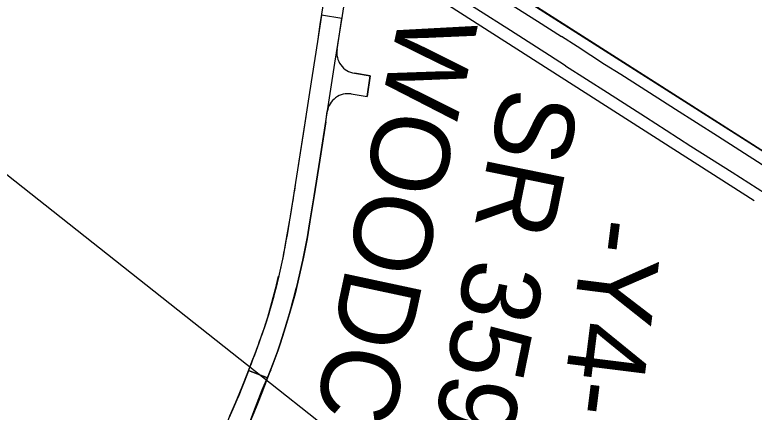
# Model space of a CAD drawing. Extents: x 1750583 to 1791140, y 783580 to 827376.
# Drawn here: x 1782431 to 1783138, y 813741 to 814121 of the extents above; entities that cross this region are included whole.
import ezdxf

# ---------------------------------------------------------------- set-up
doc = ezdxf.new("R2010")
doc.units = 0
for name, color, linetype in [('Exist CMT EOP', 7, 'Continuous'), ('Prop Dimension Text', 7, 'Continuous'), ('Prop EOT', 7, 'Continuous'), ('Prop Shade Heavy', 7, 'Continuous'), ('Sheet Plan Layout CELL', 7, 'Continuous')]:
    doc.layers.add(name, color=color, linetype=linetype)

msp = doc.modelspace()

# ---------------------------------------------------------------- linework, layer by layer
at = {"layer": 'Exist CMT EOP'}
for p, q in [((1782675.37, 813782.04), (1782682.09, 813799.73)), ((1782652.92, 813778.24), (1782644.03, 813755.44))]:
    msp.add_line(p, q, dxfattribs=at)
for points in [[(1782734.23, 814187.61), (1782728.02, 814148.04), (1782722.36, 814112.03), (1782719.85, 814095.74), (1782712.33, 814047.16), (1782706.26, 814007.67), (1782699.07, 813961.06)], [(1782957.05, 814072.69), (1782941.75, 814082.49), (1782904.59, 814106.27), (1782872.37, 814126.89), (1782853.79, 814138.65), (1782835.42, 814150.23), (1782806.48, 814168.98), (1782784.48, 814182.91)], [(1782832.73, 814177.58), (1782865.06, 814156.93), (1782903.76, 814132.24), (1782930.45, 814115.26), (1782953.36, 814100.59)], [(1782716.95, 813948.36), (1782722.21, 813982.3), (1782730.09, 814033.69), (1782736.6, 814075.08), (1782743.83, 814120.73), (1782749.51, 814158.26)], [(1783312.22, 813870.98), (1783270.66, 813897.48), (1783229.11, 813924.07), (1783187.82, 813950.57), (1783145.4, 813977.8), (1783102.46, 814005.18), (1783062.43, 814030.76), (1783037.57, 814046.7), (1783010.11, 814064.34), (1782994.61, 814073.9), (1782968.36, 814091.08), (1782953.36, 814100.59)], [(1782957.05, 814072.69), (1782997.32, 814047.07), (1783033.64, 814023.73), (1783053.56, 814011.03), (1783077.16, 813995.81), (1783116.5, 813970.95), (1783156.27, 813945.27), (1783197.33, 813919.23), (1783238.94, 813892.35), (1783280.65, 813865.79), (1783320.67, 813840.18), (1783362.13, 813813.73), (1783381.93, 813800.87)], [(1782682.52, 813871.32), (1782679.39, 813859), (1782675.06, 813842.21), (1782672.19, 813831.96), (1782668.92, 813822.02), (1782663.28, 813805.79), (1782658.53, 813792.76)], [(1782623.35, 813704.26), (1782623.39, 813704.36), (1782626.9, 813713.77), (1782632.27, 813727.44), (1782636.31, 813737.6), (1782641.85, 813750.8), (1782647.94, 813765.44), (1782653.31, 813779.27), (1782658.53, 813792.76)], [(1782594.39, 813580.74), (1782599.7, 813593.6), (1782605.42, 813607.2), (1782611.38, 813620.83), (1782615.3, 813631.65), (1782618.86, 813639.68), (1782626.38, 813658.87), (1782630.77, 813669.73), (1782635.61, 813681.75), (1782640.93, 813695.18), (1782645.99, 813707.93), (1782651.1, 813721.07), (1782656.25, 813734.24), (1782660.61, 813746.04), (1782667.1, 813762.5), (1782673.14, 813776.71), (1782675.73, 813781.86)]]:
    msp.add_lwpolyline(points, dxfattribs=at)
for points in [[(1781123.7, 814794.56), (1781151.95, 814749.7), (1781175.35, 814711.94), (1781204.02, 814667.22), (1781230.05, 814626.42), (1781255.51, 814585.11), (1781282.93, 814541.39), (1781309.04, 814500.81), (1781338.07, 814453.82), (1781362.44, 814415.66), (1781389.1, 814373.22), (1781417.2, 814328.4), (1781443.82, 814286), (1781469.22, 814245.27), (1781496.33, 814201.88), (1781523.28, 814159.28), (1781551.49, 814114.9), (1781575, 814076.8), (1781602.27, 814034.47), (1781628.68, 813992.42), (1781657.71, 813946.44), (1781682.97, 813906.24), (1781710.54, 813862.11), (1781734.73, 813823.58), (1781763.09, 813779.24), (1781788.41, 813738.38), (1781814.81, 813696.35), (1781842.37, 813653.36), (1781868.91, 813610.68), (1781895.83, 813568.71), (1781924.39, 813523.58), (1781950.61, 813481.8), (1781976.68, 813442.67), (1782004.37, 813401.37), (1782031.99, 813360.12), (1782060.77, 813317.53), (1782089.19, 813276.64), (1782119.2, 813233.31), (1782146.2, 813195.67), (1782175.13, 813155.14), (1782204.07, 813115.4), (1782233.24, 813075.72), (1782263.79, 813034.43), (1782294.03, 812994.29), (1782325.04, 812953.86), (1782354.41, 812916.21), (1782385, 812877.38), (1782417.21, 812837.26), (1782449.43, 812797.65), (1782479.54, 812761.76), (1782513.17, 812720.66), (1782543.05, 812684.98), (1782576.35, 812645.89), (1782608.48, 812608.74), (1782640.69, 812571.37), (1782677.39, 812530.96), (1782710.34, 812494.65), (1782741.2, 812460.83), (1782775.54, 812424.09), (1782810.15, 812387.02), (1782844.36, 812350.73), (1782880.69, 812313.19), (1782914.85, 812277.64), (1782949.87, 812242.16), (1782985.13, 812206.92), (1783022.44, 812170.42), (1783054.86, 812138.57), (1783094.75, 812100.54), (1783130.02, 812066.91), (1783162.74, 812036.24), (1783200.85, 812001.49), (1783239.6, 811965.96), (1783275.52, 811933.35), (1783312.46, 811900.79)], [(1782699.07, 813961.06), (1782695.87, 813940.8), (1782687.6, 813893.23), (1782679.87, 813859.05), (1782675.04, 813841.16), (1782666.84, 813815.75), (1782652.92, 813778.24)], [(1782682.09, 813799.73), (1782691.65, 813830.13), (1782703.07, 813873.65), (1782710.99, 813912.33), (1782716.95, 813948.36)]]:
    msp.add_spline(points, degree=3, dxfattribs=at)
at = {"layer": 'Prop EOT'}
for p, q in [((1782664.72, 814298.51), (1783161.32, 813980.96)), ((1782641.02, 814261.44), (1783137.62, 813943.89)), ((1782723.75, 814121.03), (1782719.85, 814095.74)), ((1782743.39, 814117.93), (1782723.75, 814121.03)), ((1782738.7, 814088.31), (1782743.39, 814117.93)), ((1782719.85, 814095.74), (1782712.33, 814047.16)), ((1782755.33, 814065.43), (1782770.52, 814063.03)), ((1782770.52, 814063.03), (1782767.41, 814043.28)), ((1782712.33, 814047.16), (1782708.5, 814022.2)), ((1782752.25, 814045.67), (1782767.41, 814043.28)), ((1782727.86, 814019.14), (1782729.36, 814028.94))]:
    msp.add_line(p, q, dxfattribs=at)
for points in [[(1782708.5, 814022.2), (1782701.56, 813977.16), (1782698.42, 813956.92), (1782694.18, 813930.37), (1782692.38, 813919.73), (1782689.87, 813905.54), (1782687.1, 813890.63), (1782683.3, 813873.14), (1782680.34, 813860.95), (1782676.08, 813844.76), (1782672.99, 813834.31), (1782669.89, 813824.5), (1782667.01, 813816.21), (1782664.33, 813808.79), (1782662.52, 813803.68), (1782659.32, 813794.9), (1782658.53, 813792.74), (1782655.75, 813785.57), (1782653.99, 813781.01)], [(1782727.86, 814019.14), (1782722.21, 813982.3), (1782716.95, 813948.36), (1782712.79, 813923.21), (1782710.11, 813907.18), (1782706.61, 813889.5), (1782702.8, 813872.5), (1782698.51, 813854.49), (1782696.15, 813845.58), (1782693.32, 813835.57), (1782691.33, 813829.11), (1782689.07, 813821.9), (1782686.5, 813813.75), (1782683.94, 813805.6), (1782682.16, 813799.93), (1782677.29, 813787.09), (1782675.13, 813781.44), (1782672.16, 813774.06)]]:
    msp.add_lwpolyline(points, dxfattribs=at)
for centre, start, end in [((1782758.45, 814085.18), 171.00203, 261.03336), ((1782749.13, 814025.91), 81.03336, 171.28117)]:
    msp.add_arc(centre, 20, start, end, dxfattribs=at)
for points in [[(1782653.99, 813781.01), (1782653.75, 813780.38), (1782653.52, 813779.76), (1782653.28, 813779.14), (1782653.05, 813778.51), (1782652.81, 813777.89), (1782652.57, 813777.27), (1782652.34, 813776.65), (1782652.1, 813776.02), (1782651.86, 813775.4), (1782651.62, 813774.78), (1782651.38, 813774.16), (1782651.14, 813773.54), (1782650.9, 813772.92), (1782650.66, 813772.29), (1782650.41, 813771.67), (1782650.17, 813771.05), (1782649.93, 813770.43), (1782649.68, 813769.81), (1782649.44, 813769.19), (1782649.19, 813768.57), (1782648.95, 813767.95), (1782648.7, 813767.34), (1782648.45, 813766.72), (1782648.21, 813766.1), (1782647.96, 813765.48), (1782647.71, 813764.86), (1782647.46, 813764.24), (1782647.21, 813763.62), (1782646.96, 813763.01), (1782646.71, 813762.39), (1782646.46, 813761.77), (1782646.21, 813761.16), (1782645.96, 813760.54), (1782645.7, 813759.92), (1782645.45, 813759.31), (1782645.19, 813758.69), (1782644.94, 813758.07), (1782644.68, 813757.46), (1782644.43, 813756.84), (1782644.17, 813756.23), (1782643.92, 813755.61), (1782643.66, 813755), (1782643.4, 813754.38), (1782643.14, 813753.77), (1782642.88, 813753.16), (1782642.62, 813752.54), (1782642.36, 813751.93), (1782642.1, 813751.32), (1782641.84, 813750.7), (1782641.58, 813750.09), (1782641.32, 813749.48), (1782641.05, 813748.87), (1782640.79, 813748.25), (1782640.52, 813747.64), (1782640.26, 813747.03), (1782639.99, 813746.42), (1782639.73, 813745.81), (1782639.46, 813745.2), (1782639.19, 813744.59), (1782638.93, 813743.98), (1782638.66, 813743.37), (1782638.39, 813742.76), (1782638.12, 813742.15), (1782637.85, 813741.54), (1782637.58, 813740.93), (1782637.31, 813740.32), (1782637.04, 813739.71), (1782636.77, 813739.1), (1782636.49, 813738.49), (1782636.21, 813737.86), (1782635.93, 813737.24), (1782635.65, 813736.61), (1782635.1, 813735.37)], [(1782672.16, 813774.06), (1782671.93, 813773.41), (1782671.69, 813772.77), (1782671.46, 813772.13), (1782671.22, 813771.49), (1782670.99, 813770.84), (1782670.75, 813770.2), (1782670.51, 813769.56), (1782670.27, 813768.92), (1782670.04, 813768.28), (1782669.8, 813767.64), (1782669.56, 813767), (1782669.32, 813766.35), (1782669.08, 813765.71), (1782668.83, 813765.07), (1782668.59, 813764.43), (1782668.35, 813763.79), (1782668.11, 813763.15), (1782667.86, 813762.51), (1782667.62, 813761.88), (1782667.37, 813761.24), (1782667.13, 813760.6), (1782666.88, 813759.96), (1782666.63, 813759.32), (1782666.39, 813758.68), (1782666.14, 813758.04), (1782665.89, 813757.41), (1782665.64, 813756.77), (1782665.39, 813756.13), (1782665.14, 813755.5), (1782664.89, 813754.86), (1782664.64, 813754.22), (1782664.39, 813753.59), (1782664.13, 813752.95), (1782663.88, 813752.31), (1782663.63, 813751.68), (1782663.37, 813751.04), (1782663.12, 813750.41), (1782662.86, 813749.77), (1782662.61, 813749.14), (1782662.35, 813748.5), (1782662.09, 813747.87), (1782661.83, 813747.23), (1782661.58, 813746.6), (1782661.32, 813745.97), (1782661.06, 813745.33), (1782660.8, 813744.7), (1782660.54, 813744.07), (1782660.28, 813743.43), (1782660.01, 813742.8), (1782659.75, 813742.17), (1782659.49, 813741.54), (1782659.22, 813740.91), (1782658.96, 813740.27), (1782658.69, 813739.64), (1782658.43, 813739.01), (1782658.16, 813738.38), (1782657.9, 813737.75), (1782657.63, 813737.12), (1782657.36, 813736.49), (1782657.09, 813735.86), (1782656.82, 813735.23), (1782656.55, 813734.6), (1782656.28, 813733.97), (1782656.01, 813733.34), (1782655.74, 813732.71), (1782655.47, 813732.08), (1782655.2, 813731.46), (1782654.93, 813730.83), (1782654.66, 813730.21), (1782654.39, 813729.59), (1782654.12, 813728.98), (1782653.86, 813728.37), (1782653.33, 813727.14)]]:
    msp.add_spline(points, degree=3, dxfattribs=at)
at = {"layer": 'Prop Shade Heavy'}
for p, q in [((1783161.38, 813980.92), (1782664.72, 814298.51)), ((1782641.02, 814261.44), (1783137.68, 813943.86)), ((1782723.75, 814121.03), (1782719.85, 814095.74)), ((1782743.39, 814117.93), (1782723.75, 814121.03)), ((1782738.7, 814088.31), (1782743.39, 814117.93)), ((1782719.85, 814095.74), (1782712.33, 814047.16)), ((1782770.52, 814063.03), (1782755.33, 814065.43)), ((1782767.41, 814043.28), (1782770.52, 814063.03)), ((1782712.33, 814047.16), (1782708.5, 814022.2)), ((1782752.25, 814045.67), (1782767.41, 814043.28)), ((1782727.86, 814019.14), (1782729.36, 814028.94)), ((1782672.16, 813774.06), (1782653.99, 813781.01)), ((1782653.99, 813781.01), (1782672.16, 813774.06))]:
    msp.add_line(p, q, dxfattribs=at)
for points in [[(1782708.5, 814022.2), (1782701.56, 813977.16), (1782698.42, 813956.92), (1782694.18, 813930.37), (1782692.38, 813919.73), (1782689.87, 813905.54), (1782687.1, 813890.63), (1782683.3, 813873.14), (1782680.34, 813860.95), (1782676.08, 813844.76), (1782672.99, 813834.31), (1782669.89, 813824.5), (1782667.01, 813816.21), (1782664.33, 813808.79), (1782662.52, 813803.68), (1782659.32, 813794.9), (1782658.53, 813792.74), (1782655.75, 813785.57), (1782653.99, 813781.01)], [(1782672.16, 813774.06), (1782675.13, 813781.44), (1782677.29, 813787.09), (1782682.16, 813799.93), (1782683.94, 813805.6), (1782686.5, 813813.75), (1782689.07, 813821.9), (1782691.33, 813829.11), (1782693.32, 813835.57), (1782696.15, 813845.58), (1782698.51, 813854.49), (1782702.8, 813872.5), (1782706.61, 813889.5), (1782710.11, 813907.18), (1782712.79, 813923.21), (1782716.95, 813948.36), (1782722.21, 813982.3), (1782727.86, 814019.14)]]:
    msp.add_lwpolyline(points, dxfattribs=at)
for centre, start, end in [((1782758.45, 814085.18), 171.00203, 261.03336), ((1782749.13, 814025.91), 81.03336, 171.28117)]:
    msp.add_arc(centre, 20, start, end, dxfattribs=at)
for points in [[(1782653.99, 813781.01), (1782653.91, 813780.8), (1782653.83, 813780.59), (1782653.75, 813780.38), (1782653.68, 813780.18), (1782653.6, 813779.97), (1782653.52, 813779.76), (1782653.44, 813779.55), (1782653.36, 813779.34), (1782653.28, 813779.14), (1782653.2, 813778.93), (1782653.13, 813778.72), (1782653.05, 813778.51), (1782652.97, 813778.31), (1782652.89, 813778.1), (1782652.81, 813777.89), (1782652.73, 813777.68), (1782652.65, 813777.48), (1782652.57, 813777.27), (1782652.49, 813777.06), (1782652.41, 813776.85), (1782652.34, 813776.65), (1782652.26, 813776.44), (1782652.18, 813776.23), (1782652.1, 813776.02), (1782652.02, 813775.82), (1782651.94, 813775.61), (1782651.86, 813775.4), (1782651.78, 813775.19), (1782651.7, 813774.99), (1782651.62, 813774.78), (1782651.54, 813774.57), (1782651.46, 813774.37), (1782651.38, 813774.16), (1782651.3, 813773.95), (1782651.22, 813773.74), (1782651.14, 813773.54), (1782651.06, 813773.33), (1782650.98, 813773.12), (1782650.9, 813772.92), (1782650.82, 813772.71), (1782650.74, 813772.5), (1782650.66, 813772.29), (1782650.57, 813772.09), (1782650.49, 813771.88), (1782650.41, 813771.67), (1782650.33, 813771.47), (1782650.25, 813771.26), (1782650.17, 813771.05), (1782650.09, 813770.85), (1782650.01, 813770.64), (1782649.93, 813770.43), (1782649.85, 813770.23), (1782649.76, 813770.02), (1782649.68, 813769.81), (1782649.6, 813769.61), (1782649.52, 813769.4), (1782649.44, 813769.19), (1782649.36, 813768.99), (1782649.28, 813768.78), (1782649.19, 813768.57), (1782649.11, 813768.37), (1782649.03, 813768.16), (1782648.95, 813767.95), (1782648.87, 813767.75), (1782648.78, 813767.54), (1782648.7, 813767.34), (1782648.62, 813767.13), (1782648.54, 813766.92), (1782648.45, 813766.72), (1782648.37, 813766.51), (1782648.29, 813766.3), (1782648.21, 813766.1), (1782648.15, 813765.95), (1782648.09, 813765.8), (1782648.03, 813765.65)], [(1782666.23, 813758.28), (1782666.28, 813758.41), (1782666.34, 813758.55), (1782666.39, 813758.68), (1782666.47, 813758.9), (1782666.55, 813759.11), (1782666.63, 813759.32), (1782666.72, 813759.53), (1782666.8, 813759.75), (1782666.88, 813759.96), (1782666.96, 813760.17), (1782667.05, 813760.38), (1782667.13, 813760.6), (1782667.21, 813760.81), (1782667.29, 813761.02), (1782667.37, 813761.24), (1782667.46, 813761.45), (1782667.54, 813761.66), (1782667.62, 813761.88), (1782667.7, 813762.09), (1782667.78, 813762.3), (1782667.86, 813762.51), (1782667.94, 813762.73), (1782668.03, 813762.94), (1782668.11, 813763.15), (1782668.19, 813763.37), (1782668.27, 813763.58), (1782668.35, 813763.79), (1782668.43, 813764.01), (1782668.51, 813764.22), (1782668.59, 813764.43), (1782668.67, 813764.65), (1782668.75, 813764.86), (1782668.83, 813765.07), (1782668.92, 813765.29), (1782669, 813765.5), (1782669.08, 813765.71), (1782669.16, 813765.93), (1782669.24, 813766.14), (1782669.32, 813766.35), (1782669.4, 813766.57), (1782669.48, 813766.78), (1782669.56, 813767), (1782669.64, 813767.21), (1782669.72, 813767.42), (1782669.8, 813767.64), (1782669.88, 813767.85), (1782669.96, 813768.06), (1782670.04, 813768.28), (1782670.12, 813768.49), (1782670.2, 813768.7), (1782670.27, 813768.92), (1782670.35, 813769.13), (1782670.43, 813769.35), (1782670.51, 813769.56), (1782670.59, 813769.77), (1782670.67, 813769.99), (1782670.75, 813770.2), (1782670.83, 813770.42), (1782670.91, 813770.63), (1782670.99, 813770.84), (1782671.07, 813771.06), (1782671.14, 813771.27), (1782671.22, 813771.49), (1782671.3, 813771.7), (1782671.38, 813771.91), (1782671.46, 813772.13), (1782671.54, 813772.34), (1782671.61, 813772.56), (1782671.69, 813772.77), (1782671.77, 813772.98), (1782671.85, 813773.2), (1782671.93, 813773.41), (1782672.01, 813773.63), (1782672.08, 813773.84), (1782672.16, 813774.06)], [(1782648.03, 813765.65), (1782648.01, 813765.6), (1782647.98, 813765.54), (1782647.96, 813765.48), (1782647.88, 813765.27), (1782647.79, 813765.07), (1782647.71, 813764.86), (1782647.63, 813764.65), (1782647.55, 813764.45), (1782647.46, 813764.24), (1782647.38, 813764.04), (1782647.3, 813763.83), (1782647.21, 813763.62), (1782647.13, 813763.42), (1782647.05, 813763.21), (1782646.96, 813763.01), (1782646.88, 813762.8), (1782646.8, 813762.6), (1782646.71, 813762.39), (1782646.63, 813762.18), (1782646.54, 813761.98), (1782646.46, 813761.77), (1782646.38, 813761.57), (1782646.29, 813761.36), (1782646.21, 813761.16), (1782646.12, 813760.95), (1782646.04, 813760.74), (1782645.96, 813760.54), (1782645.87, 813760.33), (1782645.79, 813760.13), (1782645.7, 813759.92), (1782645.62, 813759.72), (1782645.53, 813759.51), (1782645.45, 813759.31), (1782645.36, 813759.1), (1782645.28, 813758.9), (1782645.19, 813758.69), (1782645.11, 813758.49), (1782645.03, 813758.28), (1782644.94, 813758.07), (1782644.86, 813757.87), (1782644.77, 813757.66), (1782644.68, 813757.46), (1782644.6, 813757.25), (1782644.51, 813757.05), (1782644.43, 813756.84), (1782644.34, 813756.64), (1782644.26, 813756.43), (1782644.17, 813756.23), (1782644.09, 813756.02), (1782644, 813755.82), (1782643.92, 813755.61), (1782643.83, 813755.41), (1782643.74, 813755.2), (1782643.66, 813755), (1782643.57, 813754.79), (1782643.49, 813754.59), (1782643.4, 813754.38), (1782643.31, 813754.18), (1782643.23, 813753.98), (1782643.14, 813753.77), (1782643.06, 813753.57), (1782642.97, 813753.36), (1782642.88, 813753.16), (1782642.8, 813752.95), (1782642.71, 813752.75), (1782642.62, 813752.54), (1782642.54, 813752.34), (1782642.45, 813752.13), (1782642.36, 813751.93), (1782642.28, 813751.72), (1782642.19, 813751.52), (1782642.1, 813751.32), (1782642.01, 813751.11), (1782641.93, 813750.91), (1782641.84, 813750.7), (1782641.8, 813750.62), (1782641.77, 813750.53), (1782641.73, 813750.44)], [(1782659.95, 813742.64), (1782659.97, 813742.69), (1782659.99, 813742.75), (1782660.01, 813742.8), (1782660.1, 813743.01), (1782660.19, 813743.22), (1782660.28, 813743.43), (1782660.36, 813743.65), (1782660.45, 813743.86), (1782660.54, 813744.07), (1782660.62, 813744.28), (1782660.71, 813744.49), (1782660.8, 813744.7), (1782660.88, 813744.91), (1782660.97, 813745.12), (1782661.06, 813745.33), (1782661.14, 813745.54), (1782661.23, 813745.76), (1782661.32, 813745.97), (1782661.4, 813746.18), (1782661.49, 813746.39), (1782661.58, 813746.6), (1782661.66, 813746.81), (1782661.75, 813747.02), (1782661.83, 813747.23), (1782661.92, 813747.45), (1782662.01, 813747.66), (1782662.09, 813747.87), (1782662.18, 813748.08), (1782662.26, 813748.29), (1782662.35, 813748.5), (1782662.44, 813748.71), (1782662.52, 813748.93), (1782662.61, 813749.14), (1782662.69, 813749.35), (1782662.78, 813749.56), (1782662.86, 813749.77), (1782662.95, 813749.98), (1782663.03, 813750.2), (1782663.12, 813750.41), (1782663.2, 813750.62), (1782663.29, 813750.83), (1782663.37, 813751.04), (1782663.46, 813751.25), (1782663.54, 813751.47), (1782663.63, 813751.68), (1782663.71, 813751.89), (1782663.8, 813752.1), (1782663.88, 813752.31), (1782663.97, 813752.53), (1782664.05, 813752.74), (1782664.13, 813752.95), (1782664.22, 813753.16), (1782664.3, 813753.37), (1782664.39, 813753.59), (1782664.47, 813753.8), (1782664.56, 813754.01), (1782664.64, 813754.22), (1782664.72, 813754.43), (1782664.81, 813754.65), (1782664.89, 813754.86), (1782664.97, 813755.07), (1782665.06, 813755.28), (1782665.14, 813755.5), (1782665.23, 813755.71), (1782665.31, 813755.92), (1782665.39, 813756.13), (1782665.48, 813756.34), (1782665.56, 813756.56), (1782665.64, 813756.77), (1782665.72, 813756.98), (1782665.81, 813757.19), (1782665.89, 813757.41), (1782665.97, 813757.62), (1782666.06, 813757.83), (1782666.14, 813758.04), (1782666.17, 813758.12), (1782666.2, 813758.2), (1782666.23, 813758.28)], [(1782641.73, 813750.44), (1782641.68, 813750.32), (1782641.63, 813750.21), (1782641.58, 813750.09), (1782641.49, 813749.89), (1782641.4, 813749.68), (1782641.32, 813749.48), (1782641.23, 813749.27), (1782641.14, 813749.07), (1782641.05, 813748.87), (1782640.96, 813748.66), (1782640.88, 813748.46), (1782640.79, 813748.25), (1782640.7, 813748.05), (1782640.61, 813747.85), (1782640.52, 813747.64), (1782640.44, 813747.44), (1782640.35, 813747.23), (1782640.26, 813747.03), (1782640.17, 813746.83), (1782640.08, 813746.62), (1782639.99, 813746.42), (1782639.91, 813746.21), (1782639.82, 813746.01), (1782639.73, 813745.81), (1782639.64, 813745.6), (1782639.55, 813745.4), (1782639.46, 813745.2), (1782639.37, 813744.99), (1782639.28, 813744.79), (1782639.19, 813744.59), (1782639.1, 813744.38), (1782639.02, 813744.18), (1782638.93, 813743.98), (1782638.84, 813743.77), (1782638.75, 813743.57), (1782638.66, 813743.37), (1782638.57, 813743.16), (1782638.48, 813742.96), (1782638.39, 813742.76), (1782638.3, 813742.55), (1782638.21, 813742.35), (1782638.12, 813742.15), (1782638.03, 813741.94), (1782637.94, 813741.74), (1782637.85, 813741.54), (1782637.76, 813741.33), (1782637.67, 813741.13), (1782637.58, 813740.93), (1782637.49, 813740.72), (1782637.4, 813740.52), (1782637.31, 813740.32), (1782637.22, 813740.12), (1782637.13, 813739.91), (1782637.04, 813739.71), (1782636.95, 813739.51), (1782636.86, 813739.3), (1782636.77, 813739.1), (1782636.67, 813738.9), (1782636.58, 813738.69), (1782636.49, 813738.49), (1782636.4, 813738.28), (1782636.3, 813738.07), (1782636.21, 813737.86), (1782636.12, 813737.65), (1782636.02, 813737.45), (1782635.93, 813737.24), (1782635.84, 813737.03), (1782635.75, 813736.82), (1782635.65, 813736.61), (1782635.47, 813736.2), (1782635.28, 813735.78), (1782635.1, 813735.37)], [(1782653.33, 813727.14), (1782653.5, 813727.55), (1782653.68, 813727.96), (1782653.86, 813728.37), (1782653.95, 813728.57), (1782654.03, 813728.78), (1782654.12, 813728.98), (1782654.21, 813729.18), (1782654.3, 813729.39), (1782654.39, 813729.59), (1782654.48, 813729.8), (1782654.57, 813730), (1782654.66, 813730.21), (1782654.75, 813730.41), (1782654.84, 813730.62), (1782654.93, 813730.83), (1782655.02, 813731.04), (1782655.11, 813731.25), (1782655.2, 813731.46), (1782655.29, 813731.67), (1782655.38, 813731.87), (1782655.47, 813732.08), (1782655.56, 813732.29), (1782655.65, 813732.5), (1782655.74, 813732.71), (1782655.83, 813732.92), (1782655.92, 813733.13), (1782656.01, 813733.34), (1782656.1, 813733.55), (1782656.19, 813733.76), (1782656.28, 813733.97), (1782656.37, 813734.18), (1782656.46, 813734.39), (1782656.55, 813734.6), (1782656.64, 813734.81), (1782656.73, 813735.02), (1782656.82, 813735.23), (1782656.91, 813735.44), (1782657, 813735.65), (1782657.09, 813735.86), (1782657.18, 813736.07), (1782657.27, 813736.28), (1782657.36, 813736.49), (1782657.45, 813736.7), (1782657.54, 813736.91), (1782657.63, 813737.12), (1782657.72, 813737.33), (1782657.81, 813737.54), (1782657.9, 813737.75), (1782657.99, 813737.96), (1782658.07, 813738.17), (1782658.16, 813738.38), (1782658.25, 813738.59), (1782658.34, 813738.8), (1782658.43, 813739.01), (1782658.52, 813739.22), (1782658.61, 813739.43), (1782658.69, 813739.64), (1782658.78, 813739.85), (1782658.87, 813740.06), (1782658.96, 813740.27), (1782659.05, 813740.48), (1782659.14, 813740.69), (1782659.22, 813740.91), (1782659.31, 813741.12), (1782659.4, 813741.33), (1782659.49, 813741.54), (1782659.58, 813741.75), (1782659.66, 813741.96), (1782659.75, 813742.17), (1782659.82, 813742.33), (1782659.88, 813742.48), (1782659.95, 813742.64)]]:
    msp.add_open_spline(points, degree=3, dxfattribs=at)
at = {"layer": 'Sheet Plan Layout CELL'}
msp.add_lwpolyline([(1780565.25, 813264.89), (1781623.51, 814601.56), (1784200, 812561.73), (1783141.74, 811225.05)], close=True, dxfattribs=at)

# ---------------------------------------------------------------- texts
at = {"layer": 'Prop Dimension Text'}
for s, rotation, p in [('WOODCOCK DR.', 257.92802, (1782800.08, 814126.99)), ('SR 3592', 258.49109, (1782897.58, 814054.56)), ('-Y4-', 262.85009, (1782976.72, 813929.79))]:
    msp.add_text(s, height=75, rotation=rotation, dxfattribs=at).set_placement(p)

doc.saveas('drawing.dxf')
